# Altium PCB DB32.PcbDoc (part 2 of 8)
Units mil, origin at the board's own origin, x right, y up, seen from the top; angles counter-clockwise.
Board outline 3236.22 x 4456.69 mil, 8 copper layers (Top Layer, MidLayer1, MidLayer2, GND-Layer5, MidLayer3, VCC, MidLayer4, Bottom Layer), stack 61.8 mil thick; 207 components, 474 nets, 1777 pads, 1474 vias.
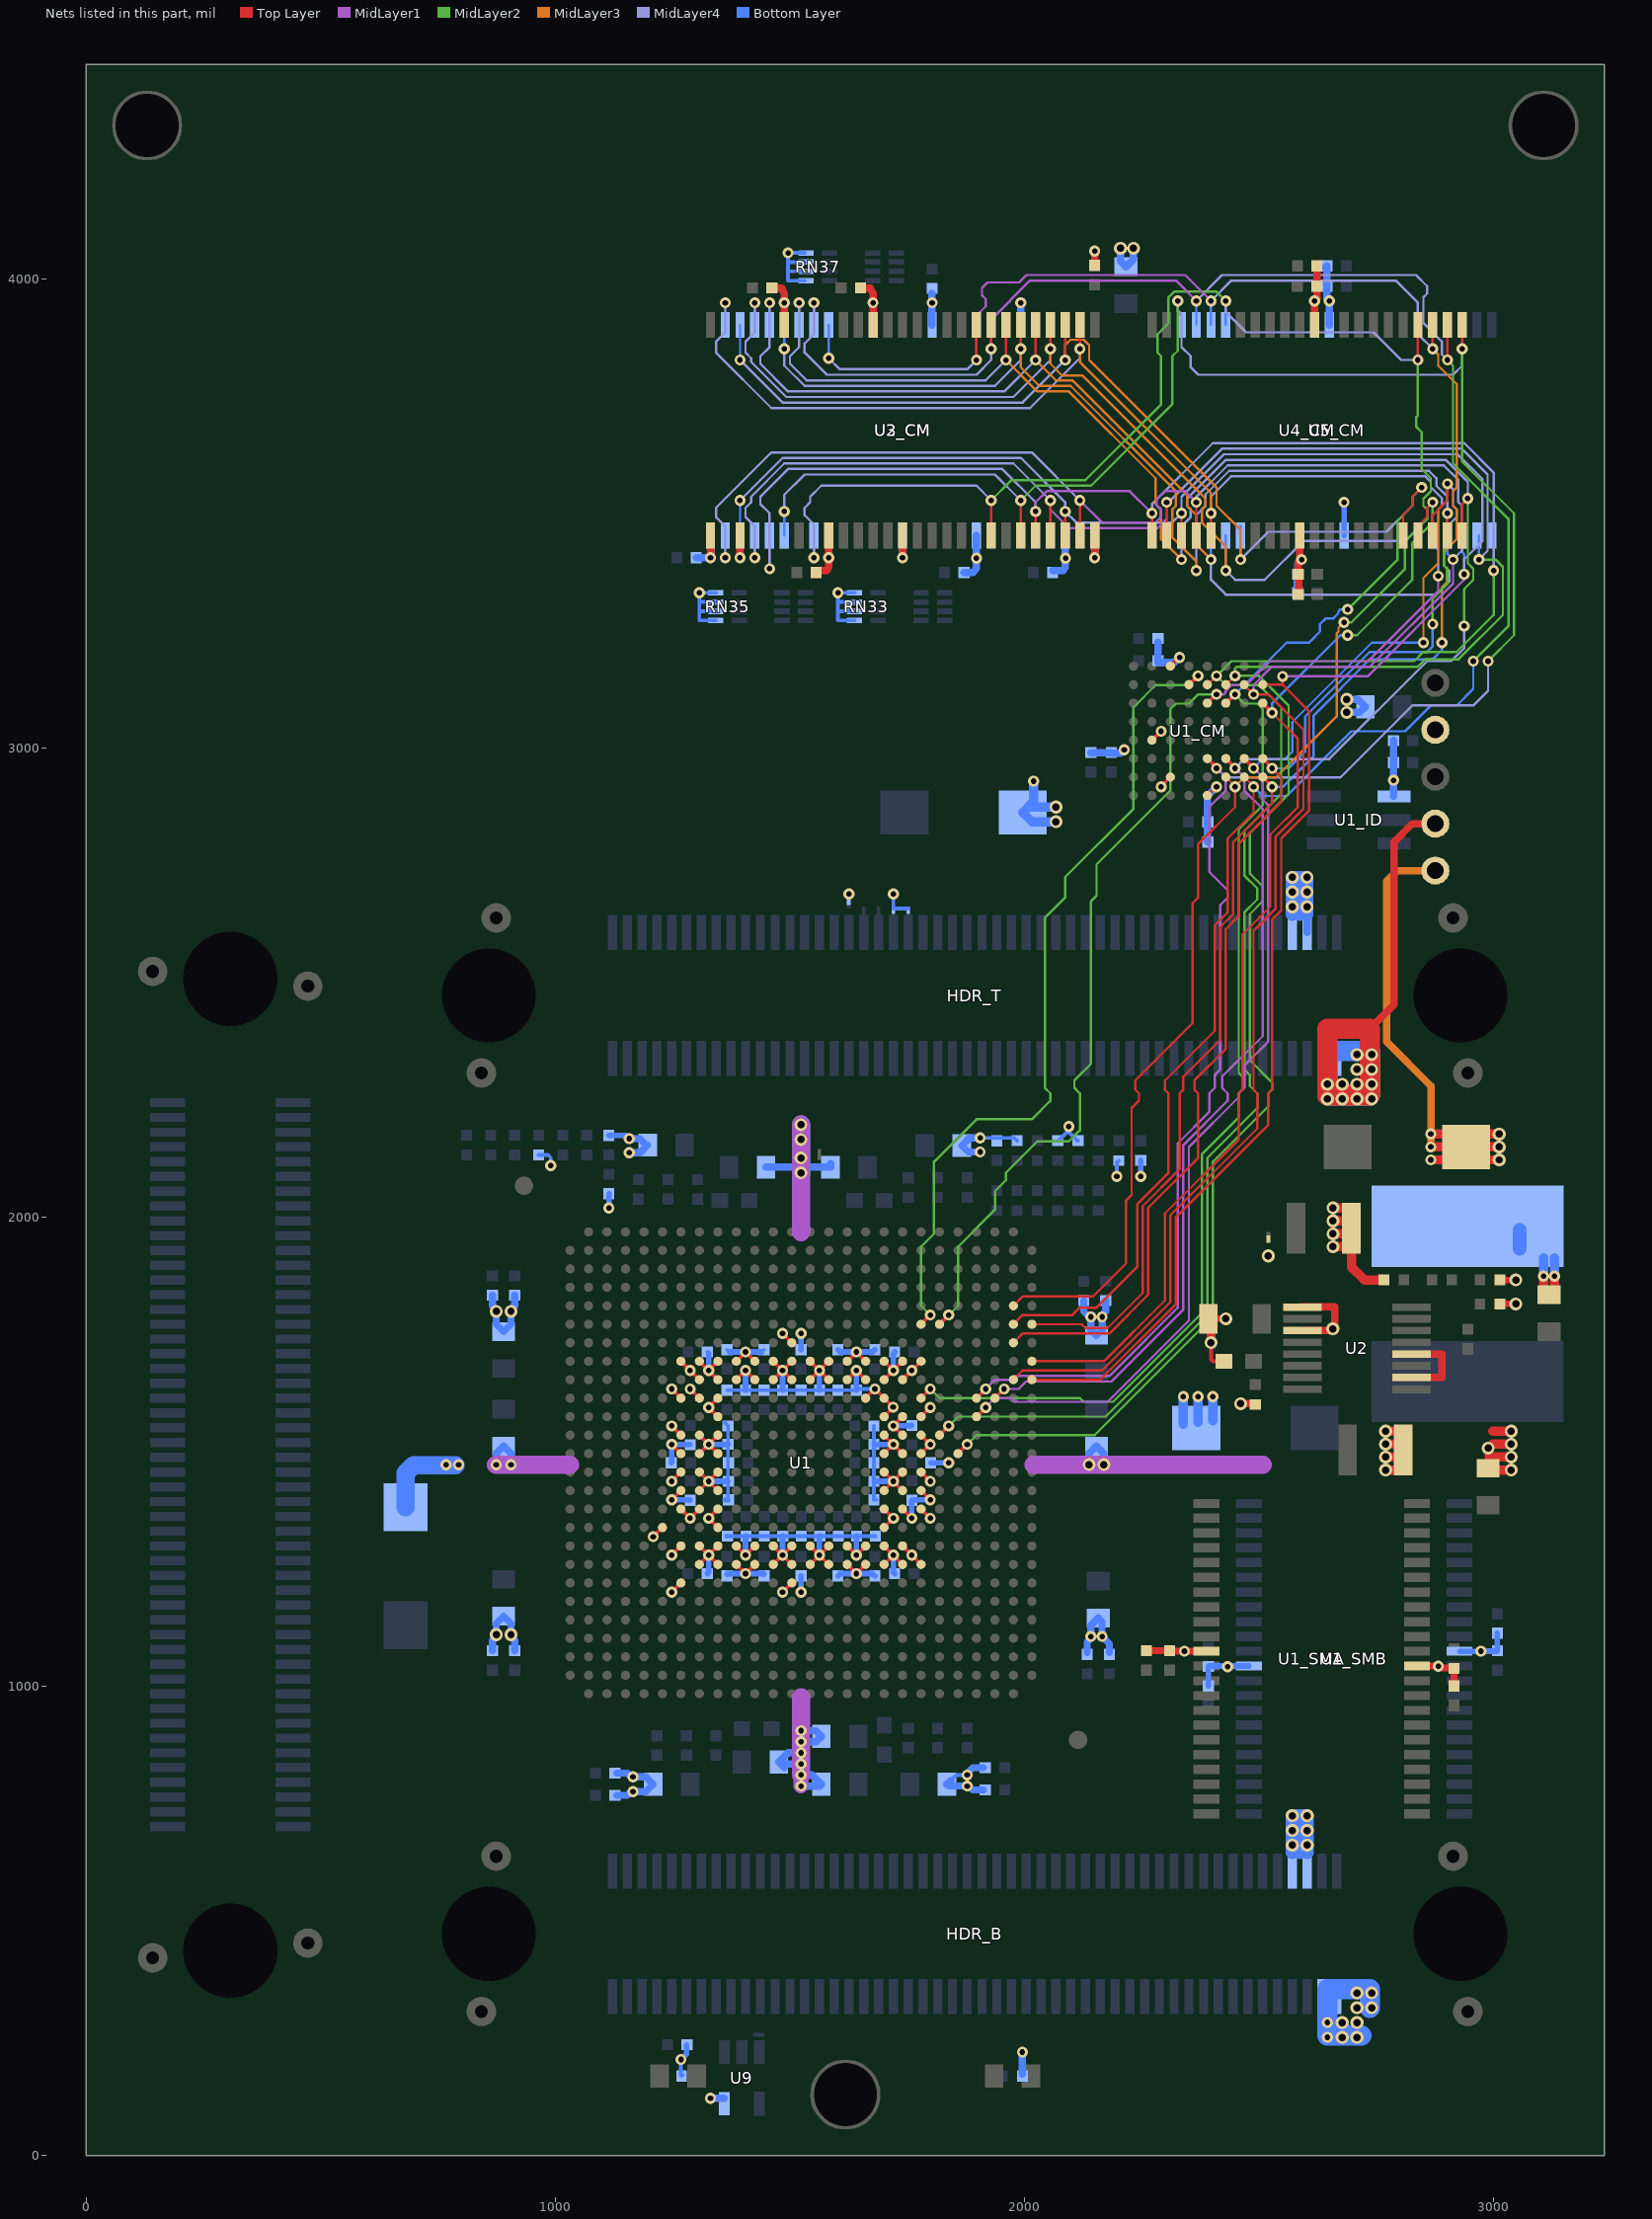
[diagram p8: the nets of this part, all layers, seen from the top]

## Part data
"Altium Logo Bot1" "Altium Logo Top1": library part D-000-0003, "Altium Logo for PCB"
C1_CM C2_CM C2_ID C3_CM C3_PL C3_SMA C3_SMB C4_SMA C4_SMB C7_CM C7_PL C8_CM C11_CM C11_PL C12_CM C15_FP C15_PL C16_FP C17_CM C17_FP C18_CM C18_FP C19_FP C20_FP C21_CM C21_FP C22_CM C22_FP C23_FP C24_FP C25_FP C62_FP C63_FP C64_FP C65_FP C66_FP C67_FP C68_FP C69_FP C70_FP C71_FP C72_FP C73_FP C74_FP C75_FP C76_FP C77_FP C78_FP C79_FP C80_FP C81_FP C82_FP C83_FP C84_FP C85_FP C86_FP C87_FP C88_FP C89_FP C90_FP C91_FP C92_FP C93_FP: library part D-101-0077, "Capacitor, Ceramic, 10nF 10% 16V 0402 (1005) X7R"
C1_FP C2_FP C3_FP C19 C22 C23_CM C24_CM C38_FP C39_FP C40_FP C41_FP C42_FP C43_FP C44_FP C45_FP: library part D-101-0087, "Capacitor, Ceramic, 10uF 10% 10V 0805 (2012) X5R"
C1_ID C1_SMA C1_SMB C2_PL C2_SMA C2_SMB C4_CM C4_FP C5_CM C5_FP C6_CM C6_FP C6_PL C7_FP C8_FP C9_CM C9_FP C10_CM C10_FP C10_PL C11_FP C12_FP C13_CM C14_CM C14_PL C15_CM C16_CM C19_CM C20_CM C46_FP C47_FP C48_FP C49_FP C50_FP C51_FP C52_FP C53_FP C54_FP C55_FP C56_FP C98: library part D-101-0080, "Capacitor, Ceramic, 0.1uF 10% 16V 0402 (1005) X7R"
C1_MB C2_MB C5_MB C17: library part D-101-0088, "Capacitor, Tantalum, 220uF 10% 10V MCCT-D (7343-31)"
C1_PL C5_PL C9_PL C13_PL C18: library part D-101-0095, "Capacitor, Ceramic, 2.2uF 10% 10V 0603 (1608) X5R"
C4_PL C8_PL C12_PL C16_PL: library part D-101-0030, "Capacitor, Ceramic, 1nF 10% 50V 0402 (1005) X7R"
C15 C20: library part D-101-0021, "Capacitor, Ceramic, 22uF -20%/+80% 10V 1210 (3225) Y5V"
C16: library part D-101-0069, "Capacitor, Ceramic, 470pF 5% 50V 0402 (1005) COG"
C21: library part D-101-0027, "Capacitor, Ceramic, 1uF 10% 25V 1206 (3216) X7R"
HDR_B HDR_L HDR_T: library part D-300-0025, "Connector, Molex Docking Station 100 Pin Male 54075"
L1_PS: library part D-102-0004, "Inductor, 2.2uH, 15A, 4R2, SMD"
L2_PL L3_PL L4_PL L5_PL: library part D-102-0002, "Inductor, Ferrite Bead 1K@100MHz 300mA 0805 (2012) BMB2A1000LN2"
LED1: library part D-153-0003, "LED, Red 0805 (2013) HSMH-C170"
LED2: library part D-153-0004, "LED, Green 0805 (2012) KP-2012SGD"
MH1 MH2 MH3: library part D-001-0001, "Mounting Hole, M3 Screw, Plated, Square Pad"
NT1 NT2 NT3 NT4 NT5 NT6 NT7 NT8: library part D-002-0002, "Net-Tie, Surface Mount, 2 x 0.4mm x 0.2mm SMT Pads - For 0.2mm Track"
R1 R2 R3 R4 R7: library part D-100-0088, "Resistor, 4K7 1% 0402 (1005)"
R5: library part D-100-0130, "Resistor, 10K 1% 0402 (1005)"
R8 R12 R14 R18 R20 R22 R23 R24 R25 R26 R27 R28: library part D-100-0131, "Resistor, 100R 1% 0402 (1005)"
R11 R16: library part D-100-0105, "Resistor, 2K7 1% 0402 (1005)"
R13: library part D-100-0128, "Resistor, 10R 1% 0402 (1005)"
R15: library part D-100-0109, "Resistor, 27K 1% 0402 (1005)"
R17: library part D-100-0132, "Resistor, 100K 1% 0402 (1005)"
R19 R21: library part D-100-0111, "Resistor, 270R 1% 0402 (1005)"
RN33 RN34 RN35 RN36 RN37 RN38: library part D-104-0001, "Resistor Network, Isolated, 4 x 100R, 5%, SMD 0402 x 4"
TP0 TP1 TP2 TP3 TP4: library part D-006-0000, "Test Point, PCB Mount with Silkscreen Box"
U1: library part D-241-0003, "FPGA, Lattice ECP-35 FN672"
U1_CM: library part D-262-0001, "S29GL256N11FFIV10, 256 Megabit (16M x 16) 3.0V Page Mode Flash Memory"
U1_ID: library part D-263-0002, "Dual Addressable Switch Plus 1KB Memory"
U1_SMA U1_SMB U4_CM U5_CM: library part D-260-0000, "K6R4016V1D-TC10T, 256K x 16-Bit SRAM, TSOP44"
U2: library part D-204-0002, "MAX1831EEE, 3A, 1MHz, Low-Voltage, Step-Down Regulators with Synchronous Rectification and Internal Switches"
U2_CM U3_CM: library part D-261-0000, "MT48LC16M16A2TG, 256 Mbit High-Speed CMOS SDRAM, 16Mb x 16Bit x 4 Banks, TSOP54"
U9: library part D-205-0001, "SN74LVC1G04DBV, Single Inverter Gate, 1.65-V to 5.5-V"

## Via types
v1: diameter 23.62, hole 11.81, Top Layer to Bottom Layer, 839 vias
v2: diameter 23.62, hole 11.81, Top Layer to Bottom Layer, tented both sides, 499 vias
v3: diameter 27.56, hole 15.75, Top Layer to Bottom Layer, 135 vias
v4: diameter 23.62, hole 11.81, Top Layer to Bottom Layer, tented top, 1 vias

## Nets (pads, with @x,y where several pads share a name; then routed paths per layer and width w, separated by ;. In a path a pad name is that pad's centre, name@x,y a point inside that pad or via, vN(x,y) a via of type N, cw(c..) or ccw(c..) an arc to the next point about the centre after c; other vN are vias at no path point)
1V2: C1_FP.1 C2_FP.1 C3_FP.1 C4_FP.1 C5_FP.1 C5_MB.1 C6_FP.1 C7_FP.1 C8_FP.1 C9_FP.1 C10_FP.1 C11_FP.1 C12_FP.1 C15.1 C15_FP.1 C16_FP.1 C17.1 C17_FP.1 C18_FP.1 C19_FP.1 C20_FP.1 C21_FP.1 C22.1 C22_FP.1 C23_FP.1 C24_FP.1 C25_FP.1 L1_PS.2 L2_PL.1 L3_PL.1 L4_PL.1 L5_PL.1 R11.1 TP4.1 U1.H8 U1.H9 U1.H10 U1.H11 U1.H16 U1.H17 U1.H18 U1.H19 U1.J9 U1.J18 U1.K8 U1.L19 U1.M19 U1.N7 U1.R7 U1.R20 U1.T19 U1.V8 U1.V9 U1.V18 U1.W8 U1.W9 U1.W10 U1.W11 U1.W16 U1.W17 U1.W18 U1.W19 | length 5303.3
  Top Layer w7.87: v1(1248.03,1397.64) U1.R7@1267.72,1417.32 ; v1(1248.03,1515.75) U1.N7@1267.72,1496.06 ; v1(1287.4,1633.86) U1.K8@1307.09,1614.17 ; U1.W8@1307.09,1259.84 v1(1326.77,1279.53) ; U1.V8@1307.09,1299.21 v1(1326.77,1279.53) ; U1.H8@1307.09,1692.91 v1(1326.77,1673.23) ; U1.W9@1346.46,1259.84 v1(1326.77,1279.53) ; U1.V9@1346.46,1299.21 v1(1326.77,1279.53) ; U1.J9@1346.46,1653.54 v1(1326.77,1673.23) ; U1.H9@1346.46,1692.91 v1(1326.77,1673.23) ; U1.W10@1385.83,1259.84 v1(1405.51,1240.16) U1.W11@1425.2,1259.84 ; U1.H10@1385.83,1692.91 v1(1405.51,1712.6) U1.H11@1425.2,1692.91 ; U1.W16@1622.05,1259.84 v1(1641.73,1240.16) U1.W17@1661.42,1259.84 ; U1.H17@1661.42,1692.91 v1(1641.73,1712.6) ; U1.W18@1700.79,1259.84 v1(1720.47,1279.53) U1.V18@1700.79,1299.21 ; U1.J18@1700.79,1653.54 U1.H19@1740.16,1692.91 ; U1.H18@1700.79,1692.91 v1(1720.47,1673.23) ; v1(1720.47,1279.53) U1.W19@1740.16,1259.84 ; U1.T19@1740.16,1377.95 v1(1759.84,1358.27) ; U1.L19@1740.16,1574.8 v1(1720.47,1555.12) U1.M19@1740.16,1535.43 U1.M19@1740.91,1535.43 ; U1.R20@1779.53,1417.32 v1(1799.21,1397.64) ; v1(1641.73,1712.6) U1.H16@1622.05,1692.91 v1(1641.73,1712.6)
  Top Layer w19.68: C15.1@2694.88,1974.41 2692.91,1976.37 C15.1@2704.72,1988.19 ; C15.1@2696.85,1948.82 2696.85,1976.37 2696.85,1893.71 2724.41,1866.14 R11.1@2766.21,1866.14 ; v1(2866.14,2122.05) C17.1@2913.39,2122.05 ; v1(2866.14,2149.61) C17.1@2913.39,2149.61 ; v1(2866.14,2177.17) C17.1@2917.32,2177.17 ; C17.1@2941.3,2122.05 v3(3011.81,2122.05) ; C17.1@2941.3,2149.61 v3(3011.81,2149.61) ; C17.1@2968.3,2122.05 C17.1@2941.02,2149.33 2968.86,2177.17 v3(3011.81,2177.17) ; C22.1@3106.3,1834.65 v1(3106.3,1874.02) ; C22.1@3129.92,1834.65 v1(3129.92,1874.02)
  Top Layer w20: v3(2657.47,1937) C15.1@2696.85,1937 ; v3(2657.47,1964.56) C15.1@2696.85,1964.56 ; v3(2657.47,1992.12) C15.1@2696.85,1992.12 ; v3(2657.47,2019.68) C15.1@2696.85,2019.68
  MidLayer1 w31.5: v1(1523.62,787.4) v1(1523.62,811.02)
  MidLayer1 w39.37: v1(874.02,1472.44) 1031.5,1472.44 ; v1(1523.62,811.02) 1523.62,976.38 ; 1523.62,1968.5 v3(1523.62,2196.85) ; 2019.68,1472.44 2507.87,1472.44
  MidLayer3 w15.75: v1(2866.14,2149.61) 2866.14,2279.53 2771.65,2374.02 2771.65,2677.17 2771.65,2716.54 2793.78,2738.67 TP4.1@2875.71,2738.67
  Bottom Layer w7.87: C19_FP.1@1323.82,1712.59 C19_FP.1@1326.77,1709.64 ; C12_FP.1@1366.14,1717.52 C12_FP.1@1371.06,1712.6 ; C23_FP.1@1439.96,1712.6 C23_FP.1@1444.88,1717.52 ; v1@1720.47,1283.46 v1@1724.41,1283.46
  Bottom Layer w11.81: C24_FP.1@1247.04,1476.37 1248.03,1477.36 v1(1248.03,1515.75) C25_FP.1@1286.41,1515.75 ; v1(1248.03,1397.64) 1286.41,1397.64 C15_FP.1@1287.4,1396.65 ; C4_FP.1@1323.82,1240.16 1326.77,1243.11 v1(1326.77,1279.53) ; v1(1326.77,1673.23) C19_FP.1@1326.77,1709.65 ; C16_FP.1@1366.14,1239.17 1367.12,1240.16 1443.89,1240.16 C5_FP.1@1444.88,1239.17 ; C12_FP.1@1371.06,1712.6 C23_FP.1@1439.96,1712.6 ; v1(1523.62,1200.79) C17_FP.1@1523.62,1235.23 ; C11_FP.1@1523.62,1717.52 1523.62,1751.61 v1(1524.02,1752.01) ; C6_FP.1@1602.36,1235.23 1607.28,1240.16 1676.18,1240.16 C18_FP.1@1681.1,1235.23 ; C22_FP.1@1602.36,1717.52 1607.28,1712.6 1676.18,1712.6 C10_FP.1@1681.1,1717.52 ; v1(1720.47,1555.12) 1758.86,1555.12 C9_FP.1@1759.84,1556.1 ; v1(1720.47,1673.23) 1720.47,1709.65 C21_FP.1@1723.43,1712.6 ; v1(1720.47,1279.53) 1720.47,1243.11 C7_FP.1@1723.43,1240.16 ; v1(1759.84,1358.27) C8_FP.1@1759.84,1396.65 ; C8_FP.1@1759.84,1396.65 1760.82,1397.64 v1(1799.21,1397.64) ; C20_FP.1@1800.19,1476.37 v1@1838.58,1476.37
  Bottom Layer w15.75: v1(874.02,1472.44) 874.02,1496.06 C1_FP.1@889.76,1511.81 905.51,1496.06 v1(905.51,1472.44) ; L4_PL.1@1448.82,2106.29 L3_PL.1@1586.61,2106.29 L3_PL.1@1586.61,2114.18 ; L2_PL.1@1488.18,826.77 L2_PL.1@1476.38,838.58 1496.06,858.27 v1(1523.62,858.27) ; L2_PL.1@1488.18,834.65 v1(1523.62,834.65) ; v3@1519.68,2122.05 v3(1523.62,2125.98) ; v1(1523.62,787.4) 1562.99,787.4 C2_FP.1@1566.93,791.34 1547.24,811.02 v1(1523.62,811.02) ; v1(1523.62,881.89) 1555.12,881.89 L5_PL.1@1566.93,893.7 1555.11,905.51 v1(1523.62,905.51) ; v3(2137.8,1472.44) 2137.8,1496.06 C3_FP.1@2153.54,1511.81 2169.29,1496.06 v3(2169.29,1472.44)
  Bottom Layer w19.68: v1(3106.3,1874.02) L1_PS.2@3106.3,1913.39 ; v1(3129.92,1874.02) L1_PS.2@3129.92,1913.39
  Bottom Layer w20: C5_MB.1@2338.59,1558.51 v1(2338.59,1617.56) ; C5_MB.1@2370.08,1562.45 v1(2370.08,1617.56) ; C5_MB.1@2401.58,1566.38 v1(2401.58,1617.56)
  Bottom Layer w29.53: L1_PS.2@3055.12,1933.07 L1_PS.2@3055.12,1972.44
  Bottom Layer w39.37: v3(1523.62,2094.49) v3(1523.62,2196.85)
  other v1: 1838.58,1476.38
  other v3: 1523.62,2165.35
3V3: C1_CM.1 C1_ID.2 C1_MB.1 C1_SMA.1 C1_SMB.1 C2_CM.1 C2_ID.1 C2_MB.1 C2_SMA.1 C2_SMB.1 C3_CM.1 C3_SMA.1 C3_SMB.1 C4_CM.1 C4_SMA.1 C4_SMB.1 C5_CM.1 C6_CM.1 C7_CM.1 C8_CM.1 C9_CM.1 C10_CM.1 C11_CM.1 C12_CM.1 C13_CM.1 C14_CM.1 C15_CM.1 C16_CM.1 C17_CM.1 C18_CM.1 C19_CM.1 C20_CM.1 C21_CM.1 C22_CM.1 C23_CM.1 C24_CM.1 C38_FP.1 C39_FP.1 C40_FP.1 C41_FP.1 C42_FP.1 C43_FP.1 C44_FP.1 C45_FP.1 C46_FP.1 C47_FP.1 C48_FP.1 C49_FP.1 C50_FP.1 C51_FP.1 C52_FP.1 C53_FP.1 C54_FP.1 C55_FP.1 C56_FP.1 C62_FP.1 C63_FP.1 C64_FP.1 C65_FP.1 C66_FP.1 C67_FP.1 C68_FP.1 C69_FP.1 C70_FP.1 C71_FP.1 C72_FP.1 C73_FP.1 C74_FP.1 C75_FP.1 C76_FP.1 C77_FP.1 C78_FP.1 C79_FP.1 C80_FP.1 C81_FP.1 C82_FP.1 C83_FP.1 C84_FP.1 C85_FP.1 C86_FP.1 C87_FP.1 C88_FP.1 C89_FP.1 C90_FP.1 C91_FP.1 C92_FP.1 C93_FP.1 C98.2 HDR_B.94 HDR_B.96 HDR_T.94 HDR_T.96 NT1.2 NT2.2 NT3.2 R1.2 R2.2 R3.2 R4.2 R7.2 R19.1 R21.1 RN33.1 RN33.2 RN33.3 RN33.4 RN35.1 RN35.2 RN35.3 RN35.4 RN37.1 RN37.2 RN37.3 RN37.4 TP1.1 U1.G13 U1.H7 U1.H12 U1.H13 U1.H14 U1.H15 U1.H20 U1.J8 U1.J10 U1.J11 U1.J12 U1.J13 U1.J14 U1.J15 U1.J16 U1.J17 U1.J19 U1.K7 U1.K9 U1.K17 U1.K18 U1.L9 U1.L18 U1.L20 U1.M7 U1.M8 U1.M9 U1.M18 U1.M20 U1.N8 U1.N9 U1.N18 U1.N19 U1.N20 U1.P7 U1.P8 U1.P9 U1.P18 U1.P19 U1.P20 U1.R8 U1.R9 U1.R18 U1.R19 U1.T7 U1.T8 U1.T9 U1.T18 U1.T20 U1.U6 U1.U9 U1.U18 U1.V7 U1.V10 U1.V11 U1.V12 U1.V13 U1.V14 U1.V15 U1.V16 U1.V17 U1.V19 U1.W12 U1.W13 U1.W14 U1.W15 U1.W20 U1.Y7 U1.Y13 U1_CM.D8 U1_CM.F1 U1_CM.F7 U1_CM.G5 U1_ID.4 U1_SMA.11 U1_SMA.33 U1_SMB.11 U1_SMB.33 U2_CM.1 U2_CM.3 U2_CM.9 U2_CM.14 U2_CM.27 U2_CM.43 U2_CM.49 U3_CM.1 U3_CM.3 U3_CM.9 U3_CM.14 U3_CM.27 U3_CM.43 U3_CM.49 U4_CM.11 U4_CM.33 U5_CM.11 U5_CM.33 U9.5 | length 9523.8
  Top Layer w5: U2_CM.9@1582.68,3433.07 U2_CM.9@1582.68,3452.76
  Top Layer w7.87: v1(1208.66,1318.9) U1.U6@1228.35,1338.58 ; v1(1248.03,1200.79) U1.Y7@1267.72,1220.47 ; v1(1248.03,1279.53) U1.V7@1267.72,1299.21 ; v1(1248.03,1437.01) U1.P7@1267.72,1456.69 ; v1(1248.03,1555.12) U1.M7@1267.72,1535.43 ; v1(1248.03,1633.86) U1.K7@1267.72,1614.17 ; U1.T7@1267.72,1377.95 v1(1287.4,1358.27) U1.T8@1307.09,1377.95 ; U1.H7@1267.72,1692.91 U1.J8@1307.09,1653.54 ; U1.R8@1307.09,1417.32 v1(1326.77,1437.01) ; U1.P8@1307.09,1456.69 v1(1326.77,1437.01) ; U1.N8@1307.09,1496.06 v1(1326.77,1515.75) ; U1.M8@1307.09,1535.43 v1(1326.77,1515.75) ; U1.U9@1346.46,1338.58 v1(1326.77,1358.27) U1.T9@1346.46,1377.95 ; U1.R9@1346.46,1417.32 v1(1326.77,1437.01) ; U1.P9@1346.46,1456.69 v1(1326.77,1437.01) ; U1.N9@1346.46,1496.06 v1(1326.77,1515.75) ; U1.M9@1346.46,1535.43 v1(1326.77,1515.75) ; U1.L9@1346.46,1574.8 v1(1326.77,1594.49) U1.K9@1346.46,1614.17 ; U1.V10@1385.83,1299.21 v1(1405.51,1279.53) U1.V11@1425.2,1299.21 ; U1.J10@1385.83,1653.54 v1(1405.51,1673.23) U1.J11@1425.2,1653.54 ; U1.W12@1464.57,1259.84 U1.V13@1503.94,1299.21 ; U1.V12@1464.57,1299.21 U1.W13@1503.94,1259.84 ; U1.J12@1464.57,1653.54 v1(1484.25,1673.23) ; U1.H12@1464.57,1692.91 v1(1484.25,1673.23) ; v1(1484.25,1200.79) U1.Y13@1503.94,1220.47 ; v1(1484.25,1751.97) U1.G13@1503.94,1732.28 ; U1.J13@1503.94,1653.54 v1(1484.25,1673.23) ; U1.H13@1503.94,1692.91 v1(1484.25,1673.23) ; U1.W14@1543.31,1259.84 U1.V15@1582.68,1299.21 ; U1.V14@1543.31,1299.21 U1.W15@1582.68,1259.84 ; U1.J14@1543.31,1653.54 v1(1562.99,1673.23) ; U1.H14@1543.31,1692.91 v1(1562.99,1673.23) ; U1.J15@1582.68,1653.54 v1(1562.99,1673.23) ; U1.H15@1582.68,1692.91 v1(1562.99,1673.23) ; U1.V16@1622.05,1299.21 v1(1641.73,1279.53) U1.V17@1661.42,1299.21 ; U1.J16@1622.05,1653.54 v1(1641.73,1673.23) U1.J17@1661.42,1653.54 ; U1.K17@1661.42,1614.17 v1(1681.1,1633.86) U1.K18@1700.79,1614.17 ; U1.U18@1700.79,1338.58 v1(1720.47,1358.27) U1.T18@1700.79,1377.95 ; U1.R18@1700.79,1417.32 v1(1720.47,1437.01) ; U1.P18@1700.79,1456.69 v1(1720.47,1437.01) ; U1.N18@1700.79,1496.06 v1(1720.47,1515.75) U1.N19@1740.16,1496.06 ; U1.M18@1700.79,1535.43 v1(1720.47,1515.75) ; U1.L18@1700.79,1574.8 v1@1720.45,1594.47 ; U1.K18@1700.79,1614.17 v1(1720,1595) ; v1(1720.47,1437.01) U1.R19@1740.16,1417.32 ; U1.V19@1740.16,1299.21 U1.W20@1779.53,1259.84 ; U1.P19@1740.16,1456.69 v1(1720.47,1437.01) ; U1.J19@1740.16,1653.54 U1.H20@1779.53,1692.91 ; U1.T20@1779.53,1377.95 v1(1799.21,1358.27) ; U1.P20@1779.53,1456.69 v1(1799.21,1437.01) ; U1.N20@1779.53,1496.06 v1(1799.21,1515.75) U1.M20@1779.53,1535.43 ; U1.L20@1779.53,1574.8 v1(1799.21,1594.49) ; U1_CM.G5@2271.65,3016.73 v1(2291.34,3035.43) ; v1@2291.34,2918.31 U1_CM.F7@2311.02,2937.99 ; U1_CM.F1@2311.02,3174.21 v1@2330.71,3193.9 ; U1_CM.D8@2389.76,2898.62 v1@2409.45,2918.31
  Top Layer w15: C4_SMA.1@2259.84,1075.78 C2_SMA.1@2309.14,1075.78 2309.92,1075 2343,1075 2343.2,1074.8 U1_SMA.33@2387.87,1074.8 ; U1_SMA.11@2836.69,1043.31 2885.83,1043.3 2889.76,1039.37 2914.45,1039.37 C1_SMA.1@2915.44,1038.38 C3_SMA.1@2915.44,1000.97 ; v1@2881.7,1043.3 v1(2882,1043)
  Top Layer w15.75: v2@1330.71,3409.45 U2_CM.1@1330.71,3452.76 ; v2(1393.7,3405.51) U2_CM.3@1393.7,3452.76 ; C7_CM.1@1461.61,3980.31 1482.28,3980.32 1488.19,3968.51 ; U2_CM.49@1488.19,3901.57 v2(1488.19,3948.82) ; v2@1488.19,3944.88 1488.19,3964.57 ; C10_CM.1@1556.1,3377.95 1578.74,3377.95 1582.68,3385.83 1582.68,3389.76 1583.46,3401.52 1583.58,3403.35 v2@1583.66,3404.53 ; U2_CM.9@1582.68,3452.76 v2@1582.68,3409.45 ; C8_CM.1@1650.59,3980.31 1671.26,3980.32 1677.17,3968.51 v2@1677.17,3944.88 ; U2_CM.43@1677.17,3901.57 v2(1677.17,3948.82) ; v2(1740.16,3405.51) U2_CM.14@1740.16,3452.76 ; v2(2149.6,3405.52) U2_CM.27@2149.61,3452.76 ; C9_CM.1@2149.6,4028.54 v2(2149.61,4059.06) ; C17_CM.1@2582.4,3371.05 C17_CM.1@2583.38,3370.07 2583.38,3394.4 v2(2590.55,3401.57) 2586.61,3405.51 U4_CM.11@2586.61,3452.76 ; C15_CM.1@2584.37,3329.71 C17_CM.1@2584.37,3370.07 ; U4_CM.33@2618.11,3901.57 v2(2618.11,3952.76) 2623.03,3957.67 C16_CM.1@2623.03,4027.55 ; v2@1582.68,3409.45 v2@1583.43,3405.66 ; v2@1582.68,3409.45 v2@1583.43,3405.66 ; v2@1583.43,3405.66 v2@1583.66,3404.53 ; v2@1583.43,3405.66 v2@1583.66,3404.53
  MidLayer4 w5: v3(2570.87,661.42) v3@2570.87,665.36
  Bottom Layer w7.87: R2.2@964.56,2132.35 984.61,2132.35 990.18,2126.78 v1(990.18,2110.18) ; v1(1157.6,2167.24) v1@1157.6,2173.35 ; v1(1267.72,204.72) 1267.72,170.78 R21.1@1269.21,169.29 R21.1@1271.65,171.73 ; C98.2@1279.53,235.24 C98.2@1280.51,236.22 ; 1307.09,3291.34 RN35.2@1342.51,3291.34 ; 1307.09,3311.02 RN35.3@1342.51,3311.02 ; v1@1326.77,1590.55 v1(1326.77,1594.49) v1@1329.73,1594.49 ; RN35.1@1342.51,3271.65 1307.09,3271.65 v1(1307.09,3330.71) RN35.4@1342.51,3330.71 ; U9.5@1359.25,122.05 U9.5@1360.23,123.03 ; C54_FP.1@1361.22,1562.01 C54_FP.1@1368.11,1555.12 1368.11,1397.63 C65_FP.1@1366.14,1397.64 ; C69_FP.1@1366.14,1630.9 C64_FP.1@1641.73,1630.9 ; C73_FP.1@1366.82,1320.3 C63_FP.1@1682.51,1320.3 ; 1496.07,4015.74 RN37.2@1531.49,4015.74 ; 1496.07,4035.43 RN37.3@1531.49,4035.43 ; RN37.1@1531.49,3996.06 1496.07,3996.06 v1(1496.07,4055.11) RN37.4@1531.49,4055.11 ; 1602.36,3291.34 RN33.2@1637.79,3291.34 ; 1602.36,3311.02 RN33.3@1637.79,3311.02 ; RN33.1@1637.79,3271.65 1602.36,3271.65 v1(1602.36,3330.71) RN33.4@1637.79,3330.71 ; C64_FP.1@1641.73,1630.9 1644.69,1633.86 v1(1681.1,1633.86) ; C56_FP.1@1679.13,1555.12 C76_FP.1@1679.13,1397.64 C76_FP.1@1685.04,1397.64 ; v2(1720.47,2688.98) 1720.47,2657.48 NT2.2@1751.97,2657.48 ; v1(1720.47,1358.27) v1@1720.47,1362.2 ; C44_FP.1@1834.64,791.34 1854.33,811.02 v1(1877.95,811.02) v1@1877.95,807.08 ; v1(1905.51,2168.86) 1978.3,2168.86 R1.2@1984.25,2162.91 ; R7.2@2070.86,2162.91 2072.36,2162.91 v2@2094.49,2185.04 ; v2(2094.49,2192.91) 2094.49,2181.1 2112.68,2162.91 R3.2@2114.17,2162.91 ; v2(2196.85,2086.61) 2196.85,2116.61 R4.2@2200.78,2120.55
  Bottom Layer w9.84: C73_FP.1@1364.74,1320.3 C73_FP.1@1366.82,1320.3
  Bottom Layer w11.81: v1(1114.17,2019.68) C80_FP.1@1114.17,2050.19 ; C81_FP.1@1114.17,2174.21 1150.63,2174.21 v1(1157.6,2167.24) ; v1(1267.72,204.72) 1279.53,216.54 C98.2@1279.53,235.24 ; v1(1326.77,1437.01) C66_FP.1@1368.11,1437.01 ; v1(1326.77,1515.75) C68_FP.1@1368.11,1515.75 ; C65_FP.1@1362.2,1397.64 C65_FP.1@1368.11,1397.64 ; v1(1405.51,1279.53) 1405.51,1319.62 C74_FP.1@1406.19,1320.3 ; C67_FP.1@1405.51,1630.9 v1(1405.51,1673.23) ; v1(1484.25,1279.53) 1484.25,1319.62 C72_FP.1@1484.93,1320.22 ; C71_FP.1@1484.25,1630.91 v1(1484.25,1673.23) ; v1(1562.99,1279.53) 1562.99,1319.62 C46_FP.1@1563.67,1320.3 ; C50_FP.1@1562.99,1630.9 v1(1562.99,1673.23) ; v1(1641.73,1279.53) 1641.73,1319.62 C70_FP.1@1642.41,1320.3 ; C64_FP.1@1641.73,1630.9 v1(1641.73,1673.23) ; C49_FP.1@1679.13,1515.75 v1(1720.47,1515.75) ; C48_FP.1@1679.21,1437.01 v1(1720.47,1437.01) ; v1@1719.02,1595 v1(1720,1595) ; v2(2248.03,2086.61) C78_FP.1@2248.03,2121.06 ; C1_SMB.1@2391.82,1000.97 C3_SMB.1@2391.82,1042.31 2392.81,1043.3 U1_SMB.11@2478.43,1043.31 ; v1(2433,1042) v1@2434.3,1043.3 ; U5_CM.11@2681.1,3452.76 v2(2681.1,3523.62) ; U1_SMB.33@2927.25,1074.79 2972.79,1074.79 v1(2973,1075) 3007.08,1075 C4_SMB.1@3007.87,1075.79 C2_SMB.1@3007.87,1113.19
  Bottom Layer w15: C85_FP.1@866.14,1075.79 866.14,1098.43 v3@874.02,1106.3 ; C82_FP.1@866.14,1833.66 866.14,1811.03 874.02,1803.15 874.02,1771.65 C39_FP.1@889.76,1755.9 905.51,1771.65 905.51,1803.15 913.38,1811.02 C83_FP.1@913.38,1833.66 ; v3(874.02,1110.24) 874.02,1133.86 C41_FP.1@889.76,1149.6 905.51,1133.85 v3(905.51,1110.24) ; v3@905.51,1106.3 913.39,1098.42 C84_FP.1@913.38,1075.79 ; C86_FP.1@1130.91,767.71 1153.54,767.71 v2@1161.42,775.59 ; C87_FP.1@1130.91,814.96 1153.55,814.96 v2@1161.42,807.09 ; v1(1157.6,2137.24) 1180.55,2137.24 C38_FP.1@1196.85,2153.54 ; v1(1157.6,2167.24) 1180.06,2167.24 C38_FP.1@1193.06,2154.24 ; v2(1165.35,775.59) 1192.91,775.59 C45_FP.1@1208.66,791.34 1192.91,807.09 v2(1165.35,807.09) ; C44_FP.1@1834.64,791.34 1838.58,787.4 v1(1877.95,787.4) ; v1@1881.89,787.4 1889.76,779.53 C88_FP.1@1912.4,779.53 ; v1@1881.89,818.9 1889.77,826.77 C89_FP.1@1912.4,826.77 ; v1(1905.51,2138.86) 1879.96,2138.84 C40_FP.1@1866.26,2152.54 1882.57,2168.84 v1(1905.51,2168.86) ; C93_FP.1@2125.98,1821.85 2125.98,1799.21 v4@2133.86,1791.34 ; C91_FP.1@2133.86,1071.85 2133.86,1094.49 v1@2141.73,1102.36 ; C43_FP.1@2157.48,1145.67 2165.35,1137.79 v1(2165.35,1106.3) 2181.1,1090.55 C90_FP.1@2181.1,1071.85 ; v1@2165.35,1791.34 2173.23,1799.21 C92_FP.1@2173.22,1821.85
  Bottom Layer w15.75: C13_CM.1@1300.19,3405.5 v2(1330.71,3405.51) ; U3_CM.27@1329.73,3437.99 U3_CM.27@1330.71,3437.01 ; v1(1330.71,122.05) U9.5@1359.25,122.05 ; v2@1330.71,3404.53 U3_CM.27@1330.71,3452.76 ; v2(1740.16,3405.51) U3_CM.14@1740.16,3452.76 ; U3_CM.43@1803.15,3901.57 C14_CM.1@1803.15,3968.5 ; C44_FP.1@1834.64,791.34 C44_FP.1@1842.52,799.21 ; C12_CM.1@1871.06,3374.01 1889.76,3374.01 1897.64,3381.89 v2(1897.64,3404.53) 1897.64,3405.51 U3_CM.9@1897.64,3452.76 ; U3_CM.49@1992.13,3901.57 v2(1992.13,3948.82) ; R19.1@1995.59,173.23 v1(1995.59,220.47) ; C11_CM.1@2060.05,3377.95 2082.68,3377.95 2086.62,3385.83 2086.62,3389.76 U3_CM.3@2086.61,3452.76 ; v2@2086.62,3409.45 v2(2087.6,3404.53) ; v1(2141.73,1106.3) 2141.73,1129.92 C43_FP.1@2157.48,1145.67 ; v4(2141.73,1787.4) 2141.73,1759.83 C42_FP.1@2153.54,1748.03 2165.35,1759.84 v1(2165.35,1787.4) ; C4_CM.1@2141.73,2990.16 C1_CM.1@2185.04,2990.16 2186.02,2989.18 2204.73,2989.18 v1(2212.6,2996.06) ; v2(2149.6,3405.52) 2149.61,3409.45 U3_CM.1@2149.61,3452.76 ; v3(2204.72,4064.96) 2204.72,4037.4 C24_CM.1@2216.53,4025.58 2232.28,4041.34 v3(2232.28,4064.96) ; C6_CM.1@2284.45,3225.39 2284.45,3182.09 2318.9,3182.09 v1@2330.22,3193.41 ; C5_CM.1@2390.74,2799.21 2389.76,2800.19 2389.76,2897.64 v1@2409.45,2917.33 ; C19_CM.1@2581.69,3330.7 C21_CM.1@2581.69,3370.07 2582.68,3371.06 2582.68,3393.7 v2(2590.55,3401.57) ; HDR_T.96@2602.36,2606.3 2602.36,2645.67 ; C20_CM.1@2641.73,4024.61 C20_CM.1@2644.68,4027.55 2644.68,3957.68 v2(2649.61,3952.76) v2@2649.61,3956.7 ; U5_CM.33@2649.88,3901.57 v2@2649.88,3944.88 ; v3(2687.01,3075.79) 2714.58,3075.79 C23_CM.1@2726.38,3087.59 2710.63,3103.35 v3(2687.01,3103.35) ; U1_ID.4@2786.42,2897.63 C1_ID.2@2786.41,3015.74
  Bottom Layer w19.68: C2_MB.1@2007.68,2874.02 v3(2066.93,2874.02) ; v1(2019.68,2929.13) 2019.68,2886.02 C2_MB.1@1996.14,2862.47 2016.09,2842.52 v3(2066.93,2842.52)
  Bottom Layer w27.56: 2570.87,645.67 v3(2570.87,661.42) v3(2570.87,692.91) v3(2570.87,724.41) v3(2602.37,724.41) v3(2602.37,692.91) v3(2602.37,661.42) 2602.36,645.67 ; 2570.87,2645.67 v3(2570.87,2724.41) v3(2602.36,2724.41) 2602.36,2645.67 ; 2586.62,645.67 2586.62,724.41 ; 2586.61,2645.67 2586.61,2724.41
  Bottom Layer w39.37: C1_MB.1@681.1,1381.97 681.1,1454.1 698,1471 v1@787.32,1471
  other v1: 2341,1075 1759.84,1279.53 767.24,1472.44 794.02,1472.44 1287.4,1673.23 1759.84,1673.22 2291.34,2917.32 2409.45,2917.32 2330.71,3192.91
  other v2: 1625.98,2688.98 2786.42,2931.1 1582.68,3405.51 1803.15,3948.82
  other v3: 874.02,1799.21 905.51,1799.21 2570.87,2661.42 2602.36,2661.42 2570.87,2692.91 2602.36,2692.91
5V0: C19.1 C20.1 HDR_B.97 HDR_B.99 HDR_T.97 HDR_T.99 R13.1 TP3.1 U2.2 U2.4 | length 2270.5
  Top Layer w15.75: v3(2460.63,1602.36) 2490.62,1602.36 R13.1@2492.12,1600.86 ; 2728.35,2393.7 2787.4,2452.75 2787.4,2799.21 2826.86,2838.67 TP3.1@2875.71,2838.67 ; U2.2@2824.58,1658.25 2889.67,1658.25 2889.67,1708.25 U2.4@2824.58,1708.25 ; C19.1@2988.18,1464.56 v3(2988.19,1507.87)
  Top Layer w20: v3(2769.84,1461.02) C20.1@2809.21,1461.02 ; v3(2769.84,1488.58) C20.1@2809.21,1488.58 ; v3(2769.84,1516.14) C20.1@2809.21,1516.14 ; v3(2769.84,1543.7) C20.1@2809.21,1543.7 ; C19.1@2998.04,1461.1 v3(3037.41,1461.1) ; 2998.04,1488.66 v3(3037.41,1488.66) ; v3@2998.04,1516.22 v3(3037.41,1516.22) ; 2998.04,1543.78 v3(3037.41,1543.78)
  Top Layer w43.31: v3@2645.67,2259.84 2645.67,2401.58 2736.22,2401.58 2736.22,2259.84 v3@2645.67,2259.84
  Bottom Layer w43.31: 2649.61,263.78 v3@2677.17,263.78 ; v3@2716.54,255.91 2718.5,255.91 2708.66,255.91 2677.17,255.9 2645.67,255.9 2645.67,354.33 2736.22,354.33 2736.22,346.46 v3@2736.22,314.96 ; v3@2645.67,2259.84 2645.67,2354.33 2736.22,2354.33 2736.22,2346.46 2736.22,2314.96 2736.22,2283.47 2736.22,2259.84 v3@2645.67,2259.84
  other v1: 2645.67,251.97 2645.67,283.46
  other v3: 2677.17,251.97 2708.66,251.97 2677.17,283.46 2708.66,283.46 2708.66,314.96 2740.16,314.96 2708.66,346.46 2740.16,346.46 2645.67,2251.97 2677.17,2251.97 2708.66,2251.97 2740.16,2251.97 2645.67,2283.46 2677.17,2283.47 2708.66,2283.47 2740.16,2283.47 2708.66,2314.96 2740.16,2314.96 2708.66,2346.46 2740.16,2346.46
AGND: C18.2 C21.1 NT7.1 R16.2 R17.2 U2.9 U2.11 | length 426
  Top Layer w7.87: v3(2397.64,1732.28) 2397.64,1696.85 2401.58,1692.91 C18.2@2425.19,1692.91
  Top Layer w13.78: C21.1@2391.73,1783.46 v3(2429.13,1783.46) ; R17.2@3013.3,1814.96 v3(3047.24,1814.96) ; R16.2@3013.3,1866.14 v3(3047.24,1866.14)
  Top Layer w15.75: U2.9@2589.19,1808.68 2591.08,1808.69 2592.58,1808.69 2661.35,1808.87 ; U2.11@2591.08,1758.25 U2.11@2592.58,1758.25 2653.67,1758.25 v3(2657.19,1761.76) ; 2657.48,1808.76 2661.35,1808.76 2661.35,1761.76 v3@2661.35,1758.26
  Top Layer w19.68: v3(2397.64,1732.28) 2397.64,1777.55 C21.1@2391.73,1783.46 C21.1@2397.64,1789.37
  other v3: 2519.68,1917.32
BUS_A1: U1.F20 U1_CM.E2 | length 1790.5
  Top Layer w7.87: U1.F20@1779.53,1771.65 v1(1799.21,1791.34) ; U1_CM.E2@2350.39,3134.84 v1(2370.08,3153.55)
  MidLayer2 w5: v1(1799.21,1791.34) 1779.53,1811.03 1779.53,1866.14 1779.53,1937.02 1807.09,1964.57 1807.09,2031.5 1807.09,2039.37 1807.09,2118.11 1897.64,2208.66 2015.75,2208.66 2055.12,2248.03 2055.12,2263.78 2043.31,2275.59 2043.31,2637.8 2086.61,2681.1 2086.61,2724.41 2232.28,2870.08 2232.28,3086.61 2279.53,3133.86 2350.39,3133.86 v1(2370.08,3153.55)
BUS_A2: U1.M21 U1_CM.D2 U2_CM.23 U3_CM.23 U4_CM.1 U5_CM.1 | length 5414.6
  Top Layer w5: U2_CM.23@2023.62,3452.76 v2(2023.62,3503.93) ; U4_CM.1@2271.65,3452.76 v1(2271.65,3500) ; U1_CM.D2@2389.76,3134.84 2390.75,3134.85 v1(2409.45,3153.54)
  Top Layer w7.87: U1.M21@1818.9,1535.43 v1(1838.59,1555.12)
  MidLayer1 w5: v2(2023.62,3503.93) 2023.62,3523.62 2047.24,3547.24 2224.41,3547.24 v1(2271.65,3500)
  MidLayer2 w5: v1(1838.59,1555.12) 1858.27,1574.8 2078.74,1574.8 2090.55,1574.8 2173.23,1574.8 2389.76,1791.34 2389.76,2125.98 2496.06,2232.28 2496.06,2263.78 2480.31,2279.53 2480.31,2303.15 2468.5,2314.96 2468.5,2649.61 2496.06,2677.17 2496.06,2700.79 2468.5,2728.35 2468.5,2822.83 2547.24,2901.57 2547.24,3086.61 2500,3133.86 2429.13,3133.86 v1(2409.45,3153.54) 2440.94,3185.04 2830.71,3185.04 2850.39,3204.72 2921.26,3204.72 3000,3283.46 v1(3000,3377.95)
  MidLayer4 w5: v2(1456.69,3381.89) 1456.69,3500 1437.01,3519.68 1437.01,3535.43 1496.06,3594.49 1952.75,3594.49 2023.62,3523.63 v2(2023.62,3503.93) ; v1(2271.65,3500) 2271.65,3519.69 2401.57,3649.61 2937.39,3649.61 3000,3587 v1(3000,3377.95)
  Bottom Layer w5: v2(1456.69,3381.89) U3_CM.23@1456.69,3452.76 ; v1(3000,3377.95) U5_CM.1@3000,3452.76
BUS_A3: U1.N22 U1_CM.C2 U2_CM.24 U3_CM.24 U4_CM.2 U5_CM.2 | length 5426.8
  Top Layer w5: U2_CM.24@2055.12,3452.76 v2(2055.11,3527.55) ; U4_CM.2@2303.15,3452.76 v1(2303.15,3523.62) ; U1_CM.C2@2429.13,3134.84 2430.12,3134.85 v1(2448.82,3153.54)
  Top Layer w7.87: U1.N22@1858.27,1496.06 v1(1877.96,1515.75)
  MidLayer1 w5: v2(2055.11,3527.55) 2055.12,3507.87 2094.49,3468.5 2283.46,3468.5 2303.15,3488.19 v1(2303.15,3523.62)
  MidLayer2 w5: v1(1877.96,1515.75) 1897.64,1535.43 2078.74,1535.43 2090.55,1535.43 2149.61,1535.43 2401.57,1787.4 2401.57,2118.11 2519.68,2236.22 2519.68,2263.78 2527.56,2271.65 2527.56,2287.4 2480.31,2334.65 2480.31,2645.67 2507.87,2673.23 2507.87,2704.72 2480.31,2732.28 2480.31,2755.91 ; 2480.31,2744.09 2480.31,2818.9 2562.99,2901.57 2562.99,3090.55 2500,3153.54 v1(2448.82,3153.54) 2448.82,3169.29 2452.76,3173.23 2838.58,3173.23 2854.33,3188.98 2925.2,3188.98 3019.68,3283.46 3019.68,3385.83 3003.94,3401.57 v1(2968.5,3401.57)
  MidLayer4 w5: v2(1425.2,3405.51) 1425.2,3472.44 1405.51,3492.13 1405.51,3511.81 1417.32,3523.62 1417.32,3535.43 1488.19,3606.3 1976.37,3606.3 v2(2055.11,3527.55) ; v1(2303.15,3523.62) 2307.09,3523.62 2421.26,3637.8 2932.21,3637.79 2987,3583 2987,3420.07 v1(2968.5,3401.57)
  Bottom Layer w5: v2(1425.2,3405.51) U3_CM.24@1425.2,3452.76 ; v1(2968.5,3401.57) U5_CM.2@2968.5,3452.76
BUS_A4: U1.J26 U1_CM.A2 U2_CM.25 U3_CM.25 U4_CM.3 U5_CM.3 | length 4668
  Top Layer w5: U1.J26@2015.75,1653.54 2078.74,1653.54 2090.55,1653.54 2161.42,1653.54 2322.83,1814.96 2322.83,2000 2519.68,2196.85 2519.68,2263.78 2527.56,2271.65 2527.56,2633.86 2547.24,2653.54 2547.24,2763.78 ; U2_CM.25@2086.61,3452.76 v2(2086.61,3503.93) ; U4_CM.3@2334.64,3452.76 v1(2334.64,3500) ; U1_CM.A2@2507.87,3134.84 2550.19,3134.85 ; 2547.24,2748.03 2547.24,2807.09 2606.3,2866.14 2606.3,3078.74 2550.19,3134.85 ; v1(2550.19,3152.55) 2550.19,3134.85
  MidLayer1 w5: v1(2550.19,3152.55) 2731.29,3152.55 2937.01,3358.27 v1(2937.01,3370.08)
  MidLayer4 w5: v2(1393.7,3527.56) 1484.25,3618.11 1992.62,3618.11 2086.61,3524.12 v2(2086.61,3503.93) 2110.23,3480.32 2314.96,3480.32 v1(2334.64,3500) 2334.64,3535.43 2425.19,3625.98 2923.02,3625.98 2976,3573 2976,3441 2937.01,3402.01 v1(2937.01,3370.08)
  Bottom Layer w5: U3_CM.25@1393.7,3452.76 v2(1393.7,3527.56) ; U5_CM.3@2933.07,3452.76 U5_CM.3@2933.07,3430.12 ; v1(2937.01,3370.08) 2937.01,3377.95 2937.01,3413.39 2933.07,3417.32 U5_CM.3@2933.07,3430.12 ; U5_CM.3@2937.01,3434.05 U5_CM.3@2933.07,3430.12
BUS_A5: U1.J25 U1_CM.B2 U2_CM.26 U3_CM.26 U4_CM.4 U5_CM.4 | length 4880.3
  Top Layer w5: U1.J25@1976.38,1653.54 1996.06,1673.23 2078.74,1673.23 2090.55,1673.23 2165.35,1673.23 2311.02,1818.9 2311.02,2003.94 2496.06,2188.98 2496.06,2263.78 2488.19,2271.65 2488.19,2610.24 2535.43,2657.48 2535.43,2767.72 ; U2_CM.26@2118.11,3452.76 v2(2118.11,3527.55) ; U4_CM.4@2366.14,3452.76 v1(2366.14,3523.62) ; U1_CM.B2@2468.5,3134.84 2468.51,3133.86 v1(2488.19,3114.17) 2519.69,3114.17 2594.49,3039.37 2594.49,2870.08 2535.43,2811.02 2535.43,2755.91
  MidLayer1 w5: v2(2118.11,3527.55) 2165.34,3480.32 2279.53,3480.32 2291.34,3492.13 2291.34,3507.87 2281.65,3517.56 2281.65,3529.68 2299.21,3547.24 2342.52,3547.24 v1(2366.14,3523.62) ; v1(2488.19,3114.17) 2488.19,3133.86 2527.56,3173.23 2736.22,3173.23 2913.39,3350.39 v1(2913.39,3401.57)
  MidLayer4 w5: v2(1362.2,3405.51) 1362.2,3472.44 1342.52,3492.13 1342.52,3511.81 1460.63,3629.92 2015.74,3629.92 v2(2118.11,3527.55) ; v1(2366.14,3523.62) 2366.14,3535.43 2433.07,3602.36 2893.7,3602.36 2924.7,3571.36 2924.7,3524.11 2933.07,3515.75 2933.07,3421.26 v1(2913.39,3401.57)
  Bottom Layer w5: v2(1362.2,3405.51) U3_CM.26@1362.2,3452.76 ; U5_CM.4@2905.51,3448.82 U5_CM.4@2901.57,3452.76 2901.57,3413.39 v1(2913.39,3401.57)
BUS_A6: U1.F21 U1_CM.D3 U2_CM.29 U3_CM.29 U4_CM.5 U5_CM.5 | length 4747
  Top Layer w5: v2(2118.1,3850.39) U2_CM.29@2118.11,3901.57 ; U4_CM.5@2397.64,3452.76 v1(2397.64,3500)
  Top Layer w7.87: U1.F21@1818.9,1771.65 v1(1838.59,1791.34) ; U1_CM.D3@2389.77,3095.48 v1(2409.45,3114.18)
  MidLayer1 w5: v1(2409.45,3114.18) 2425.2,3114.18 2429.13,3118.11 2429.13,3122.05 2440.94,3133.86 2472.44,3133.86 2523.62,3185.04 2732.28,3185.04 2881.89,3334.65 v1(2881.89,3366.14)
  MidLayer2 w5: v1(1838.59,1791.34) 1858.27,1811.03 1858.27,1866.14 1858.27,1937.01 1937.01,2015.75 1937.01,2031.5 1937.01,2043.31 1937.01,2055.12 1960.63,2078.74 1960.63,2094.49 2027.56,2161.42 2094.49,2161.42 2118.11,2185.04 2118.11,2263.78 2106.3,2275.59 2106.3,2291.34 2141.73,2326.77 2141.73,2673.23 2153.54,2685.04 2153.54,2751.97 2311.02,2909.45 2311.02,3082.68 2322.83,3094.49 2350.39,3094.49 2370.08,3114.18 v1(2409.45,3114.18)
  MidLayer3 w5: v2(2118.1,3850.39) 2118.11,3822.84 2397.64,3543.31 v1(2397.64,3500)
  MidLayer4 w5: v2(1362.2,3948.82) 1362.2,3885.83 1342.52,3866.14 1342.52,3842.52 1460.63,3724.41 2011.81,3724.41 2118.1,3830.7 v2(2118.1,3850.39) ; v1(2397.64,3500) 2397.64,3535.93 2440.45,3578.74 2854.33,3578.74 2866.14,3566.93 2866.14,3555.86 2889.76,3532.24 2889.76,3515.75 2881.89,3507.87 v1(2881.89,3366.14)
  Bottom Layer w5: U3_CM.29@1362.2,3901.59 v2(1362.2,3948.82) ; U5_CM.5@2870.08,3452.76 2870.08,3433.07 2881.89,3421.26 v1(2881.89,3366.14)
BUS_A7: U1.K20 U1_CM.C3 U2_CM.30 U3_CM.30 U4_CM.18 U5_CM.18 | length 5049.2
  Top Layer w5: v2(2086.61,3826.77) U2_CM.30@2086.61,3901.57 ; U4_CM.18@2807.09,3452.76 2807.09,3496.06 2826.77,3515.75 2826.77,3535.43 v1(2846.46,3555.12)
  Top Layer w7.87: U1.K20@1779.53,1614.17 v1(1799.21,1633.86) ; U1_CM.C3@2429.14,3095.48 v1(2448.82,3114.17)
  MidLayer2 w5: v1(1799.21,1633.86) 1818.9,1614.17 2078.74,1614.17 2090.55,1614.17 2118.11,1614.17 2125.98,1606.3 2188.98,1606.3 2377.95,1795.27 2377.95,2133.86 2456.69,2212.6 2456.69,2263.78 2468.5,2275.59 2468.5,2295.28 2456.69,2307.09 2456.69,2826.77 2507.87,2877.95 2507.87,3082.68 2496.06,3094.49 2468.5,3094.49 v1(2448.82,3114.17) ; v1(2688.98,3295.28) 2795.28,3401.57 2795.28,3484.25 2826.77,3515.75 2826.77,3535.43 v1(2846.46,3555.12)
  MidLayer3 w5: v2(2086.61,3826.77) 2086.61,3858.26 2098.43,3870.08 2125.98,3870.08 2137.8,3858.27 2137.8,3826.77 2409.45,3555.12 2409.45,3515.75 2460.63,3464.57 v2(2460.63,3401.57)
  MidLayer4 w5: v2(1393.7,3826.77) 1484.25,3736.22 1996.06,3736.22 v2(2086.61,3826.77) ; v2(2460.63,3401.57) 2519.68,3460.63 2771.65,3460.63 2826.77,3515.75 2826.77,3535.43 v1(2846.46,3555.12)
  Bottom Layer w5: v2(1393.7,3826.77) U3_CM.30@1393.7,3901.57 ; v1(2448.82,3114.17) 2559.06,3224.41 2606.3,3224.41 2610.24,3228.35 2629.92,3248.03 2629.92,3263.78 2641.73,3275.59 2657.48,3275.59 2669.29,3287.4 2669.29,3291.34 2673.23,3295.28 v1(2688.98,3295.28) ; v2(2460.63,3401.57) U5_CM.18@2460.63,3452.76 U5_CM.18@2460.63,3472.44
BUS_A8: U1.H26 U1_CM.A3 U2_CM.31 U3_CM.31 U4_CM.19 U5_CM.19 | length 4681.6
  Top Layer w5: U1.H26@2015.75,1692.91 2078.74,1692.91 2090.55,1692.91 2169.29,1692.91 2299.21,1822.83 2299.21,2007.87 2456.69,2165.35 2456.69,2263.78 2464.57,2271.65 2464.57,2602.36 2523.62,2661.42 2523.62,2814.96 2582.68,2874.02 2582.68,3019.68 v1(2527.56,3074.8) ; v2(2055.11,3850.39) U2_CM.31@2055.12,3901.57 ; U4_CM.19@2838.58,3452.76 2838.58,3472.44 2858.27,3492.13 2858.27,3511.81 v1(2870.08,3523.62)
  Top Layer w7.87: U1_CM.A3@2507.88,3095.48 v1(2527.56,3074.8)
  MidLayer2 w5: v1(2688.98,3240.16) 2708.66,3240.16 2826.77,3358.27 2826.77,3366.14 2826.77,3437.01 2870.08,3480.31 v1(2870.08,3523.62)
  MidLayer3 w5: v2(2055.11,3850.39) 2055.11,3818.9 2080.55,3793.46 2123.86,3793.46 2370.08,3547.24 2385.83,3531.5 2385.83,3515.28 2385.36,3515.28 2377.95,3507.87 2377.95,3480.32 2429.13,3429.13 v1(2429.13,3377.95)
  MidLayer4 w5: v2(1425.2,3948.82) 1425.2,3885.83 1421.26,3881.89 1405.51,3866.14 1405.51,3842.52 1417.32,3830.71 1417.32,3822.83 1492.13,3748.03 1976.38,3748.03 2055.11,3826.77 v2(2055.11,3850.39) ; v1(2429.13,3377.95) 2448.82,3358.27 2511.81,3358.27 2594.49,3440.94 2811.02,3440.94 2858.27,3488.19 2858.27,3511.81 v1(2870.08,3523.62)
  Bottom Layer w5: U3_CM.31@1425.2,3901.57 v2(1425.2,3948.82) ; v1(2429.13,3377.95) U5_CM.19@2429.13,3452.76 ; v1(2527.56,3074.8) 2527.56,3094.49 2673.23,3240.16 v1(2688.98,3240.16)
BUS_A9: U1.L23 U1_CM.B6 U2_CM.32 U3_CM.32 U4_CM.20 U5_CM.20 | length 5210
  Top Layer w5: v2(2023.62,3826.77) U2_CM.32@2023.62,3901.57 ; U4_CM.20@2870.08,3452.76 2870.08,3496.06 2901.57,3527.56 v1(2901.57,3562.99)
  Top Layer w7.87: U1.L23@1897.64,1574.8 v1(1917.33,1594.49) ; U1_CM.B6@2468.5,2977.36 v1@2488.19,2957.68
  MidLayer1 w5: v1(1917.33,1594.49) 1937.01,1614.17 1972.44,1614.17 1980.32,1606.3 2078.74,1606.3 2090.55,1606.3 2177.17,1606.3 2350.39,1779.53 2350.39,2149.61 2457.07,2256.28 2457.07,2263.4 2456.69,2263.78 2468.5,2275.59 2468.5,2322.83 2519.68,2374.02 2519.68,2732.28 ; v1@2488.19,2957.68 2488.68,2957.19 2507.87,2938 2507.87,2937.01 2507.88,2889.75 2519.66,2877.98 2519.69,2708.66
  MidLayer3 w5: v2(2023.62,3826.77) 2066.93,3783.46 2102.36,3783.46 2122.05,3763.78 2346.46,3539.37 2346.46,3515.75 2366.14,3496.06 2366.14,3433.07 v2(2397.64,3401.57) ; v1(2850.39,3224.41) 2850.39,3362.2 2881.89,3393.7 2881.89,3507.87 2901.57,3527.56 ; 2901.57,3527.56 v1(2901.57,3562.99)
  MidLayer4 w5: v2(1456.69,3948.82) 1456.69,3854.33 1437.01,3834.65 1437.01,3818.9 1496.06,3759.84 1956.69,3759.84 v2(2023.62,3826.77) ; v2(2397.64,3401.57) 2397.64,3358.27 2429.13,3326.77 2877.95,3326.77 2905.51,3354.33 2905.51,3377.95 2893.7,3389.76 2893.7,3464.57 2921.26,3492.13 2921.26,3507.87 2913.39,3515.75 2913.39,3551.18 v1(2901.57,3562.99)
  Bottom Layer w5: U3_CM.32@1456.69,3901.57 v2(1456.69,3948.82) ; v2(2397.64,3401.57) U5_CM.20@2397.64,3452.76 ; v1(2488.19,2956.69) 2507.87,2976.38 2555.12,2976.38 2570.87,2992.13 2570.87,3055.12 2740.16,3224.41 v1(2850.39,3224.41)
BUS_A10: U1.G25 U1_CM.A6 U2_CM.33 U3_CM.33 U4_CM.21 U5_CM.21 | length 4697.7
  Top Layer w5: U1.G25@1976.38,1732.28 1996.06,1751.97 2078.74,1751.97 2090.55,1751.97 2181.1,1751.97 2263.78,1834.65 2263.78,2019.69 2370.08,2125.98 2370.08,2263.78 2362.2,2271.65 2362.2,2291.34 2429.13,2358.27 2429.13,2614.17 2456.69,2641.73 2456.69,2752.14 ; v2(1992.12,3850.39) U2_CM.33@1992.13,3901.57 ; 2456.69,2740.16 2456.69,2795.27 2547.24,2885.83 2547.24,2937.01 v1(2527.56,2956.69) v1@2527.56,2957.68 ; U4_CM.21@2901.57,3452.76 v1(2901.57,3500)
  Top Layer w7.87: U1_CM.A6@2507.87,2977.36 v1@2527.56,2957.68
  MidLayer2 w5: v1(2870.08,3263.78) 2870.08,3318.9 2901.57,3350.39 2901.57,3381.89 2893.7,3389.76 2893.7,3468.5 2901.57,3476.38 v1(2901.57,3500)
  MidLayer3 w5: v2(1992.12,3850.39) 1992.12,3811.03 2031.5,3771.65 2098.43,3771.65 2322.83,3547.24 2322.83,3515.75 2314.96,3507.87 2314.96,3448.82 2366.14,3397.64 v1(2366.14,3377.95)
  MidLayer4 w5: v2(1488.19,3850.39) 1488.19,3814.96 1531.5,3771.65 1937.01,3771.65 1992.12,3826.77 v2(1992.12,3850.39) ; v1(2366.14,3377.95) 2366.14,3496.06 2385.36,3515.28 2385.83,3515.28 2385.83,3540.11 2436.27,3590.55 2862.2,3590.55 2877.95,3574.8 2877.95,3559.06 2901.57,3535.43 v1(2901.57,3500)
  Bottom Layer w5: v2(1488.19,3850.39) U3_CM.33@1488.19,3901.57 ; v1(2366.14,3377.95) U5_CM.21@2366.14,3452.76 ; v1(2527.56,2956.69) 2562.99,2956.69 2598.43,2992.13 2598.43,3066.93 2736.22,3204.72 2858.27,3204.72 2870.08,3216.54 v1(2870.08,3263.78)
BUS_A11: U1.K24 U1_CM.C6 U2_CM.34 U3_CM.34 U4_CM.22 U5_CM.22 | length 5029.2
  Top Layer w5: v2(1960.62,3826.77) U2_CM.34@1960.63,3901.57 ; U4_CM.22@2933.07,3452.76 2933.07,3519.68 v1(2944.88,3531.5)
  Top Layer w7.87: U1.K24@1937.01,1614.17 v1(1956.7,1633.86) ; U1_CM.C6@2429.13,2977.36 v1@2448.82,2957.68
  MidLayer1 w5: v1(1956.7,1633.86) 1987.21,1633.86 2002.95,1649.61 2078.74,1649.61 2090.55,1649.61 2185.04,1649.61 2338.58,1803.15 2338.58,2153.54 2433.07,2248.03 2433.07,2263.78 2421.26,2275.59 2421.26,2299.21 2507.87,2385.83 2507.87,2870.08 2468.51,2909.44 2468.51,2937.99 2449.31,2957.19 v1@2448.82,2957.68
  MidLayer2 w5: v1(2937.01,3259.84) 2937.01,3338.58 2952.76,3354.33 2956.69,3358.27 2956.69,3381.89 2944.88,3393.7 v1(2944.88,3531.5)
  MidLayer3 w5: v2(1960.62,3826.77) 2027.56,3759.84 2094.49,3759.84 2279.53,3574.8 2279.53,3519.68 2291.34,3507.87 2291.34,3444.88 v2(2334.65,3401.57)
  MidLayer4 w5: v2(1519.68,3948.82) 1519.68,3854.33 1500,3834.65 1500,3818.9 1535.43,3783.46 1917.32,3783.46 v2(1960.62,3826.77) ; v2(2334.65,3401.57) 2334.65,3472.44 2354.33,3492.13 2354.33,3507.87 2346.46,3515.75 2346.46,3531.5 2429.13,3614.17 2897.64,3614.17 2944.88,3566.93 v1(2944.88,3531.5) ; v1(2448.82,2956.69) 2468.5,2976.38 2649.61,2976.38 2858.27,3185.04 2909.45,3185.04 2937.01,3212.6 v1(2937.01,3259.84)
  Bottom Layer w5: U3_CM.34@1519.68,3901.57 v2(1519.68,3948.82) ; v2(2334.65,3401.57) U5_CM.22@2334.65,3452.76
BUS_A12: U1.K23 U1_CM.D6 U2_CM.22 U3_CM.22 U4_CM.23 U5_CM.23 | length 5536.4
  Top Layer w5: U2_CM.22@1992.13,3452.76 v2(1992.12,3527.55) ; v2(2933.07,3850.39) U4_CM.23@2933.07,3901.57
  Top Layer w7.87: U1.K23@1897.64,1614.17 v1(1917.33,1633.86) ; U1_CM.D6@2389.76,2977.36 v1@2409.45,2957.68
  MidLayer1 w5: v1(1917.33,1633.86) 1937.01,1653.54 1972.44,1653.54 1980.32,1661.42 2078.74,1661.42 2090.55,1661.42 2181.1,1661.42 2259.84,1740.16 ; 2204.72,1685.04 2326.77,1807.09 2326.77,2157.48 2393.7,2224.41 2393.7,2263.78 2405.51,2275.59 2405.51,2303.15 2417.32,2314.96 2417.32,2665.35 2433.07,2681.1 2433.07,2696.85 2393.7,2736.22 2393.7,2874.02 2429.14,2909.46 2429.14,2937 v1(2409.45,2956.69) 2409.45,2957.68 v1@2409.94,2957.19
  MidLayer2 w5: v2(1992.12,3527.55) 2023.62,3559.06 2141.73,3559.06 2314.96,3732.28 2314.96,3834.64 2326.77,3846.46 v2(2326.77,3952.76) ; v2(2933.07,3850.39) 2933.07,3610.24 3043.31,3500 3043.31,3240.16 v1(2988.19,3185.04)
  MidLayer4 w5: v2(1488.19,3503.94) 1488.19,3539.37 1531.5,3582.68 1937,3582.68 v2(1992.12,3527.55) ; v2(2326.77,3952.76) 2326.77,3933.07 2334.65,3925.2 2334.65,3854.33 2354.33,3834.65 2354.33,3811.02 2370.08,3795.28 2913.39,3795.28 2933.07,3814.96 v2(2933.07,3850.39) ; v1(2409.45,2956.69) 2429.13,2937.01 2673.23,2937.01 2826.77,3090.55 2956.69,3090.55 2988.19,3122.05 v1(2988.19,3185.04)
  Bottom Layer w5: U3_CM.22@1488.19,3452.76 v2(1488.19,3503.94) ; v2(2326.77,3952.76) 2326.77,3929.13 2334.65,3921.26 U5_CM.23@2334.65,3901.57
BUS_A13: U1.F25 U1_CM.B7 U2_CM.35 U3_CM.35 U4_CM.24 U5_CM.24 | length 4901.1
  Top Layer w5: v2(1929.13,3850.39) U2_CM.35@1929.13,3901.57 ; U1.F25@1976.38,1771.65 1996.06,1791.34 2078.74,1791.34 2090.55,1791.34 2102.36,1791.34 2118.11,1807.09 2153.54,1807.09 2240.16,1893.7 2240.16,2027.56 2307.09,2094.49 2307.09,2263.78 2299.21,2271.65 2299.21,2290.85 2405.51,2397.14 2405.51,2622.05 2433.07,2649.61 2433.07,2756.79 ; 2433.07,2740.16 2433.07,2807.09 2488.19,2862.21 2488.19,2918.31 U1_CM.B7@2468.5,2937.99 ; v2(2901.57,3826.77) U4_CM.24@2901.57,3901.57
  MidLayer1 w5: v2(1929.13,3850.39) 1929.13,3913.39 2011.81,3996.06 2322.83,3996.06 v2(2366.14,3952.76)
  MidLayer2 w5: v2(2901.57,3826.77) 2913.39,3814.96 2913.39,3606.3 3031.5,3488.19 3031.5,3259.84 v1(2956.69,3185.04)
  MidLayer4 w5: v2(1551.18,3948.82) 1551.18,3881.89 1531.5,3862.2 1531.5,3842.52 1578.74,3795.28 1897.64,3795.28 1929.13,3826.77 v2(1929.13,3850.39) ; v2(2366.14,3952.76) 2421.26,4007.87 2834.65,4007.87 2858.27,3984.25 2858.27,3968.5 2850.39,3960.63 2850.39,3905.51 2889.76,3866.14 2889.76,3838.58 v2(2901.57,3826.77)
  Bottom Layer w5: U3_CM.35@1551.18,3901.57 v2(1551.18,3948.82) ; U5_CM.24@2366.14,3901.57 v2(2366.14,3952.76) ; v1(2488.19,2917.32) 2507.87,2897.64 2559.06,2897.64 2696.85,3035.43 2811.02,3035.43 2866.14,3090.55 2921.26,3090.55 2956.69,3125.98 v1(2956.69,3185.04)
BUS_A14: U1.F26 U1_CM.A7 U2_CM.36 U3_CM.36 U4_CM.25 U5_CM.25 | length 4583.4
  Top Layer w5: v2(1897.63,3826.77) U2_CM.36@1897.64,3901.57 ; U1.F26@2015.75,1771.65 2078.74,1771.65 2090.55,1771.65 2122.05,1771.65 2129.92,1763.78 2177.17,1763.78 2251.97,1838.58 2251.97,2023.62 2330.71,2102.36 2330.71,2263.78 2338.58,2271.65 2338.58,2299.21 2417.32,2377.95 2417.32,2618.11 2444.88,2645.67 2444.88,2754.47 ; 2444.88,2744.09 2444.88,2799.21 2527.56,2881.89 v1(2527.56,2917.32) v1@2527.56,2918.31 ; v2(2870.08,3850.39) U4_CM.25@2870.08,3901.57
  Top Layer w7.87: U1_CM.A7@2507.87,2937.99 v1@2527.56,2918.31
  MidLayer1 w5: v2(1897.63,3826.77) 1897.64,3921.26 1917.32,3940.94 1917.32,3956.69 1909.45,3964.57 1909.45,3980.32 1921.26,3992.13 1988.19,3992.13 2003.94,4007.87 2342.52,4007.87 v2(2397.64,3952.76)
  MidLayer3 w5: v2(2870.08,3850.39) 2881.89,3838.58 2881.89,3814.96 2921.26,3775.59 2921.26,3555.12 2913.39,3547.24 2913.39,3515.75 2921.26,3507.87 2921.26,3444.88 2893.7,3417.32 2893.7,3389.76 2901.57,3381.89 2901.57,3354.33 2889.76,3342.52 v1(2889.76,3224.41)
  MidLayer4 w5: v2(1582.68,3830.71) 1606.3,3807.09 1877.95,3807.09 v2(1897.63,3826.77) ; v2(2397.64,3952.76) 2440.94,3996.06 2791.34,3996.06 2838.58,3948.82 2838.58,3881.89 v2(2870.08,3850.39)
  Bottom Layer w5: v2(1582.68,3830.71) U3_CM.36@1582.68,3901.57 ; U5_CM.25@2397.64,3901.57 v2(2397.64,3952.76) ; v1(2527.56,2917.32) 2551.18,2917.32 2616.5,2982.65 2616.5,3069.26 2736.22,3188.98 2870.08,3188.98 2889.76,3208.66 v1(2889.76,3224.41)
BUS_A15: U1.E25 U1_CM.C7 U2_CM.20 U3_CM.20 U4_CM.26 U5_CM.26 | length 4675.5
  Top Layer w5: U2_CM.20@1929.13,3452.76 v2(1929.13,3527.55) ; U1.E25@1976.38,1811.02 1996.06,1830.71 2078.74,1830.71 2090.55,1830.71 2145.67,1830.71 2216.54,1901.57 2216.54,2035.43 2228.35,2047.24 2228.35,2232.28 2244.09,2248.03 2244.09,2263.78 2236.22,2271.65 2236.22,2291.34 2358.27,2413.39 2358.27,2669.29 2370.08,2681.1 2370.08,2795.28 2448.82,2874.02 v1(2448.82,2917.32) 2448.82,2918.31 U1_CM.C7@2429.13,2937.99 ; v2(2838.58,3826.77) U4_CM.26@2838.58,3901.57
  MidLayer2 w5: v2(1929.13,3527.55) 1972.44,3570.87 2129.92,3570.87 2291.34,3732.28 2291.34,3834.65 2283.46,3842.52 2283.46,3881.89 2293.31,3891.73 2307.09,3905.51 2307.09,3960.63 2318.9,3972.44 2409.45,3972.44 v2(2429.13,3952.76) ; v1(2681.1,3267.72) 2696.85,3267.72 2811.02,3381.89 2811.02,3440.94 2858.27,3488.19 2858.27,3507.87 2850.39,3515.75 2850.39,3531.5 2866.14,3547.25 2866.14,3574.8 2846.46,3594.49 2846.46,3673.23 2834.64,3685.04 2834.64,3704.72 2838.58,3708.66 v2(2838.58,3826.77)
  MidLayer3 w5: v1(2448.82,2917.32) 2468.5,2937.01 2535.43,2937.01 2665.35,3066.93 2665.35,3244.09 2669.29,3248.03 2669.29,3255.91 v1(2681.1,3267.72)
  MidLayer4 w5: v2(1551.18,3405.51) 1551.18,3476.38 1531.5,3496.06 1531.5,3511.81 1543.31,3523.62 1543.31,3535.43 1566.93,3559.06 1897.63,3559.06 v2(1929.13,3527.55) ; v2(2429.13,3952.76) 2429.13,3929.13 2472.44,3885.83 2744.09,3885.83 2803.15,3826.77 v2(2838.58,3826.77)
  Bottom Layer w5: v2(1551.18,3405.51) U3_CM.20@1551.18,3452.76 ; U5_CM.26@2429.13,3901.57 v2(2429.13,3952.76)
